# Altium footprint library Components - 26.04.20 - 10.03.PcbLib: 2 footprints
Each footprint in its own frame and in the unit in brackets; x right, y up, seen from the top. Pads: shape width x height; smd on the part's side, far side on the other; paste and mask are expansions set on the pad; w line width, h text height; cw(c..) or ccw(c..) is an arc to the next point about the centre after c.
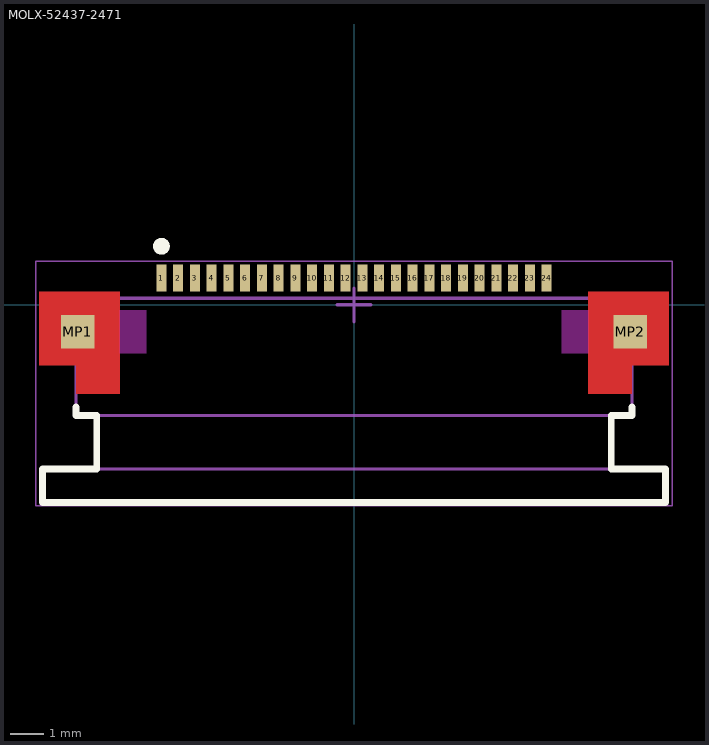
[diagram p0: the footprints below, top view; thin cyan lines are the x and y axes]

## MOLX-52437-2471 [mm] "FPC Connector, 24-Leads, Right Angle, Pitch 0.5 mm, SMT"
height 2.052
pads (26):
  rect 0.3x0.8 smd: 1(-5.75,0.8) 2(-5.25,0.8) 3(-4.75,0.8) 4(-4.25,0.8) 5(-3.75,0.8) 6(-3.25,0.8) 7(-2.75,0.8) 8(-2.25,0.8) 9(-1.75,0.8) 10(-1.25,0.8) 11(-0.75,0.8) 12(-0.25,0.8) 13(0.25,0.8) 14(0.75,0.8) 15(1.25,0.8) 16(1.75,0.8) 17(2.25,0.8) 18(2.75,0.8) 19(3.25,0.8) 20(3.75,0.8) 21(4.25,0.8) 22(4.75,0.8) 23(5.25,0.8) 24(5.75,0.8)
  rect 1x1 smd: MP1(-8.25,-0.8) MP2(8.25,-0.8)
Top Layer:
  region: 7,0.4 9.4,0.4 9.4,-1.8 8.3,-1.8 8.3,-2.65 7,-2.65
  region: -7,0.4 -9.4,0.4 -9.4,-1.8 -8.3,-1.8 -8.3,-2.65 -7,-2.65
Top Overlay:
  circle w0.25: c-5.75,1.75 r0.125
  lines w0.2: -8.301,-3.05 -8.301,-3.3 -7.681,-3.3 -7.681,-4.9 -9.3,-4.9 ; 8.3,-3.05 8.3,-3.3 7.679,-3.3 7.679,-4.9 9.3,-4.9 ; -9.3,-4.9 -9.3,-4.9 ; -9.3,-4.9 -9.3,-5.9 9.3,-5.9 9.3,-4.9 ; 9.3,-4.9 9.3,-4.9
Keep-Out Layer:
  rectangle: 6.2,-1.45 7,-0.15
  region: -6.2,-0.15 -7,-0.15 -7,-1.45 -6.2,-1.45
Mechanical 13:
  lines w0.1: -7.681,-4.9 -9.3,-4.9 -9.3,-5.9 9.3,-5.9 9.3,-4.9 7.679,-4.9 ; -7.681,-4.9 -7.681,-3.3 ; -7.681,-4.9 7.679,-4.9 ; -7.681,-3.3 -8.301,-3.3 -8.301,0.2 8.3,0.2 8.3,-3.3 7.679,-3.3 ; -7.681,-3.3 7.679,-3.3 ; 7.679,-4.9 7.679,-3.3
Mechanical 15:
  lines w0.05: -9.5,-6 9.5,-6 9.5,1.3 -9.5,1.3 -9.5,-6
  lines w0.1: -0.5,0 0.5,0 ; 0,-0.5 0,0.5
3D body "524372471.stp": height 2.05, standoff 0.01, extent -9.3,-5.9 9.3,0.9

## PCBComponent_1 [mm]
